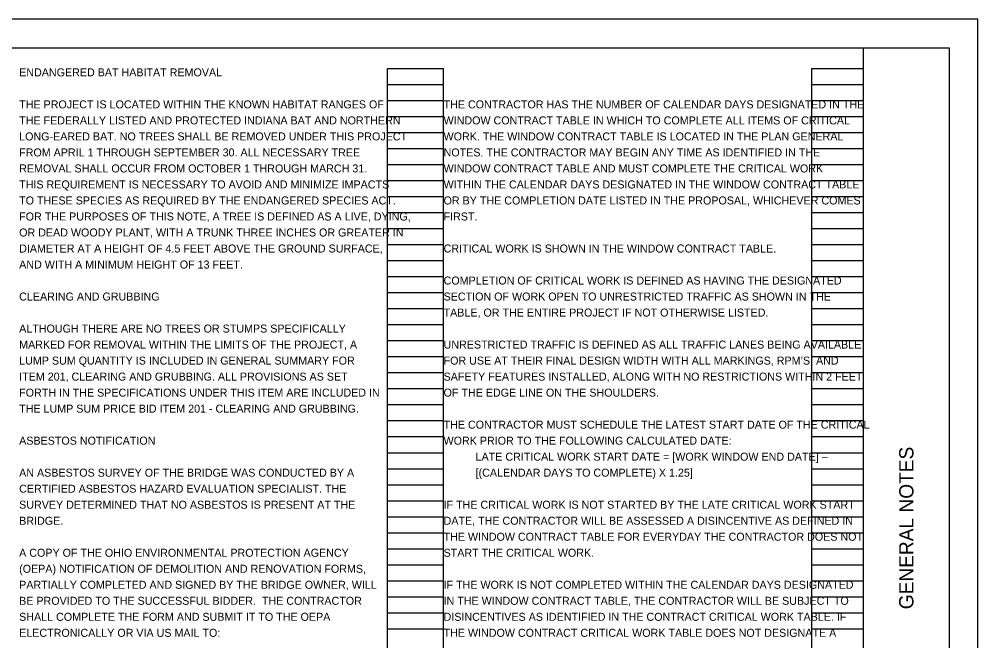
# Model space of a CAD drawing. Extents: x 0 to 84.3, y -13.4 to 22.
# Drawn here: x 17.24 to 34, y 11.13 to 22 of the extents above; entities that cross this region are included whole.
import ezdxf

# ---------------------------------------------------------------- set-up
doc = ezdxf.new("R2010")
doc.units = 0
for name, color, linetype in [('SH_Border', 7, 'Continuous'), ('SH_Cut_Line', 7, 'Continuous'), ('SH_Data', 7, 'Continuous'), ('SH_Text', 7, 'Continuous')]:
    doc.layers.add(name, color=color, linetype=linetype)

msp = doc.modelspace()

# ---------------------------------------------------------------- linework, layer by layer
at = {"layer": 'SH_Border'}
msp.add_line((32, 0.5), (32, 21.5), dxfattribs=at)
msp.add_lwpolyline([(1.5, 21.5), (33.5, 21.5), (33.5, 0.5), (1.5, 0.5)], close=True, dxfattribs=at)
at = {"layer": 'SH_Cut_Line'}
msp.add_lwpolyline([(0, 0), (34, 0), (34, 22), (0, 22)], close=True, dxfattribs=at)
at = {"layer": 'SH_Data'}
for p, q in [((23.68, 0.98), (23.68, 21.14)), ((23.68, 21.14), (24.66, 21.14)), ((24.66, 0.98), (24.66, 21.14)), ((31.1, 0.98), (31.1, 21.14)), ((31.1, 21.14), (32, 21.14)), ((32, 0.98), (32, 21.14)), ((23.68, 20.86), (24.66, 20.86)), ((31.1, 20.86), (32, 20.86)), ((23.68, 20.58), (24.66, 20.58)), ((31.1, 20.58), (32, 20.58)), ((23.68, 20.3), (24.66, 20.3)), ((31.1, 20.3), (32, 20.3)), ((23.68, 20.02), (24.66, 20.02)), ((31.1, 20.02), (32, 20.02)), ((23.68, 19.74), (24.66, 19.74)), ((31.1, 19.74), (32, 19.74)), ((23.68, 19.46), (24.66, 19.46)), ((31.1, 19.46), (32, 19.46)), ((23.68, 19.18), (24.66, 19.18)), ((31.1, 19.18), (32, 19.18)), ((23.68, 18.9), (24.66, 18.9)), ((31.1, 18.9), (32, 18.9)), ((23.68, 18.62), (24.66, 18.62)), ((31.1, 18.62), (32, 18.62)), ((23.68, 18.34), (24.66, 18.34)), ((31.1, 18.34), (32, 18.34)), ((23.68, 18.06), (24.66, 18.06)), ((31.1, 18.06), (32, 18.06)), ((23.68, 17.78), (24.66, 17.78)), ((31.1, 17.78), (32, 17.78)), ((23.68, 17.5), (24.66, 17.5)), ((31.1, 17.5), (32, 17.5)), ((23.68, 17.22), (24.66, 17.22)), ((31.1, 17.22), (32, 17.22)), ((23.68, 16.94), (24.66, 16.94)), ((31.1, 16.94), (32, 16.94)), ((23.68, 16.66), (24.66, 16.66)), ((31.1, 16.66), (32, 16.66)), ((23.68, 16.38), (24.66, 16.38)), ((31.1, 16.38), (32, 16.38)), ((23.68, 16.1), (24.66, 16.1)), ((31.1, 16.1), (32, 16.1)), ((23.68, 15.82), (24.66, 15.82)), ((31.1, 15.82), (32, 15.82)), ((23.68, 15.54), (24.66, 15.54)), ((31.1, 15.54), (32, 15.54)), ((23.68, 15.26), (24.66, 15.26)), ((31.1, 15.26), (32, 15.26)), ((23.68, 14.98), (24.66, 14.98)), ((31.1, 14.98), (32, 14.98)), ((23.68, 14.7), (24.66, 14.7)), ((31.1, 14.7), (32, 14.7)), ((23.68, 14.42), (24.66, 14.42)), ((31.1, 14.42), (32, 14.42)), ((23.68, 14.14), (24.66, 14.14)), ((31.1, 14.14), (32, 14.14)), ((23.68, 13.86), (24.66, 13.86)), ((31.1, 13.86), (32, 13.86)), ((23.68, 13.58), (24.66, 13.58)), ((31.1, 13.58), (32, 13.58)), ((23.68, 13.3), (24.66, 13.3)), ((31.1, 13.3), (32, 13.3)), ((23.68, 13.02), (24.66, 13.02)), ((31.1, 13.02), (32, 13.02)), ((23.68, 12.74), (24.66, 12.74)), ((31.1, 12.74), (32, 12.74)), ((23.68, 12.46), (24.66, 12.46)), ((31.1, 12.46), (32, 12.46)), ((23.68, 12.18), (24.66, 12.18)), ((31.1, 12.18), (32, 12.18)), ((23.68, 11.9), (24.66, 11.9)), ((31.1, 11.9), (32, 11.9)), ((23.68, 11.62), (24.66, 11.62)), ((31.1, 11.62), (32, 11.62)), ((23.68, 11.34), (24.66, 11.34)), ((31.1, 11.34), (32, 11.34))]:
    msp.add_line(p, q, dxfattribs=at)

# ---------------------------------------------------------------- texts
msp.add_text('GENERAL NOTES', height=0.25, rotation=90, dxfattribs=at).set_placement((32.875, 11.682))
at = {"layer": 'SH_Text'}
for s, p in [('ENDANGERED BAT HABITAT REMOVAL', (17.24, 21)), ('THE PROJECT IS LOCATED WITHIN THE KNOWN HABITAT RANGES OF ', (17.24, 20.44)), ('THE CONTRACTOR HAS THE NUMBER OF CALENDAR DAYS DESIGNATED IN THE ', (24.66, 20.44)), ('THE FEDERALLY LISTED AND PROTECTED INDIANA BAT AND NORTHERN', (17.24, 20.16)), ('WINDOW CONTRACT TABLE IN WHICH TO COMPLETE ALL ITEMS OF CRITICAL ', (24.66, 20.16)), ('LONG-EARED BAT. NO TREES SHALL BE REMOVED UNDER THIS PROJECT', (17.24, 19.88)), ('WORK. THE WINDOW CONTRACT TABLE IS LOCATED IN THE PLAN GENERAL ', (24.66, 19.88)), ('FROM APRIL 1 THROUGH SEPTEMBER 30. ALL NECESSARY TREE ', (17.24, 19.6)), ('NOTES. THE CONTRACTOR MAY BEGIN ANY TIME AS IDENTIFIED IN THE ', (24.66, 19.6)), ('REMOVAL SHALL OCCUR FROM OCTOBER 1 THROUGH MARCH 31.', (17.24, 19.32)), ('WINDOW CONTRACT TABLE AND MUST COMPLETE THE CRITICAL WORK ', (24.66, 19.32)), ('THIS REQUIREMENT IS NECESSARY TO AVOID AND MINIMIZE IMPACTS', (17.24, 19.04)), ('WITHIN THE CALENDAR DAYS DESIGNATED IN THE WINDOW CONTRACT TABLE ', (24.66, 19.04)), ('TO THESE SPECIES AS REQUIRED BY THE ENDANGERED SPECIES ACT.', (17.24, 18.76)), ('OR BY THE COMPLETION DATE LISTED IN THE PROPOSAL, WHICHEVER COMES ', (24.66, 18.76)), ('FOR THE PURPOSES OF THIS NOTE, A TREE IS DEFINED AS A LIVE, DYING,', (17.24, 18.48)), ('FIRST.', (24.66, 18.48)), ('OR DEAD WOODY PLANT, WITH A TRUNK THREE INCHES OR GREATER IN', (17.24, 18.2)), ('DIAMETER AT A HEIGHT OF 4.5 FEET ABOVE THE GROUND SURFACE,', (17.24, 17.92)), ('CRITICAL WORK IS SHOWN IN THE WINDOW CONTRACT TABLE.', (24.66, 17.92)), ('AND WITH A MINIMUM HEIGHT OF 13 FEET.', (17.24, 17.64)), ('COMPLETION OF CRITICAL WORK IS DEFINED AS HAVING THE DESIGNATED ', (24.66, 17.36)), ('CLEARING AND GRUBBING', (17.24, 17.08)), ('SECTION OF WORK OPEN TO UNRESTRICTED TRAFFIC AS SHOWN IN THE ', (24.66, 17.08)), ('TABLE, OR THE ENTIRE PROJECT IF NOT OTHERWISE LISTED. ', (24.66, 16.8)), ('ALTHOUGH THERE ARE NO TREES OR STUMPS SPECIFICALLY ', (17.24, 16.52)), ('MARKED FOR REMOVAL WITHIN THE LIMITS OF THE PROJECT, A ', (17.24, 16.24)), ('UNRESTRICTED TRAFFIC IS DEFINED AS ALL TRAFFIC LANES BEING AVAILABLE ', (24.66, 16.24)), ('LUMP SUM QUANTITY IS INCLUDED IN GENERAL SUMMARY FOR ', (17.24, 15.96)), ('FOR USE AT THEIR FINAL DESIGN WIDTH WITH ALL MARKINGS, RPM’S, AND ', (24.66, 15.96)), ('ITEM 201, CLEARING AND GRUBBING. ALL PROVISIONS AS SET ', (17.24, 15.68)), ('SAFETY FEATURES INSTALLED, ALONG WITH NO RESTRICTIONS WITHIN 2 FEET ', (24.66, 15.68)), ('FORTH IN THE SPECIFICATIONS UNDER THIS ITEM ARE INCLUDED IN ', (17.24, 15.4)), ('OF THE EDGE LINE ON THE SHOULDERS.', (24.66, 15.4)), ('THE LUMP SUM PRICE BID ITEM 201 - CLEARING AND GRUBBING.', (17.24, 15.12)), ('THE CONTRACTOR MUST SCHEDULE THE LATEST START DATE OF THE CRITICAL ', (24.66, 14.84)), ('ASBESTOS NOTIFICATION', (17.24, 14.56)), ('WORK PRIOR TO THE FOLLOWING CALCULATED DATE: ', (24.66, 14.56)), ('LATE CRITICAL WORK START DATE = [WORK WINDOW END DATE] – ', (25.22, 14.28)), ('AN ASBESTOS SURVEY OF THE BRIDGE WAS CONDUCTED BY A', (17.24, 14)), ('[(CALENDAR DAYS TO COMPLETE) X 1.25]', (25.22, 14)), ('CERTIFIED ASBESTOS HAZARD EVALUATION SPECIALIST. THE', (17.24, 13.72)), ('SURVEY DETERMINED THAT NO ASBESTOS IS PRESENT AT THE', (17.24, 13.44)), ('IF THE CRITICAL WORK IS NOT STARTED BY THE LATE CRITICAL WORK START ', (24.66, 13.44)), ('BRIDGE.', (17.24, 13.16)), ('DATE, THE CONTRACTOR WILL BE ASSESSED A DISINCENTIVE AS DEFINED IN ', (24.66, 13.16)), ('THE WINDOW CONTRACT TABLE FOR EVERYDAY THE CONTRACTOR DOES NOT ', (24.66, 12.88)), ('A COPY OF THE OHIO ENVIRONMENTAL PROTECTION AGENCY', (17.24, 12.6)), ('START THE CRITICAL WORK.', (24.66, 12.6)), ('(OEPA) NOTIFICATION OF DEMOLITION AND RENOVATION FORMS,', (17.24, 12.32)), ('PARTIALLY COMPLETED AND SIGNED BY THE BRIDGE OWNER, WILL', (17.24, 12.04)), ('IF THE WORK IS NOT COMPLETED WITHIN THE CALENDAR DAYS DESIGNATED ', (24.66, 12.04)), ('BE PROVIDED TO THE SUCCESSFUL BIDDER.  THE CONTRACTOR', (17.24, 11.76)), ('IN THE WINDOW CONTRACT TABLE, THE CONTRACTOR WILL BE SUBJECT TO ', (24.66, 11.76)), ('SHALL COMPLETE THE FORM AND SUBMIT IT TO THE OEPA', (17.24, 11.48)), ('DISINCENTIVES AS IDENTIFIED IN THE CONTRACT CRITICAL WORK TABLE. IF ', (24.66, 11.48)), ('ELECTRONICALLY OR VIA US MAIL TO:', (17.24, 11.2)), ('THE WINDOW CONTRACT CRITICAL WORK TABLE DOES NOT DESIGNATE A ', (24.66, 11.2))]:
    msp.add_text(s, height=0.14, dxfattribs=at).set_placement(p)

doc.saveas('drawing.dxf')
